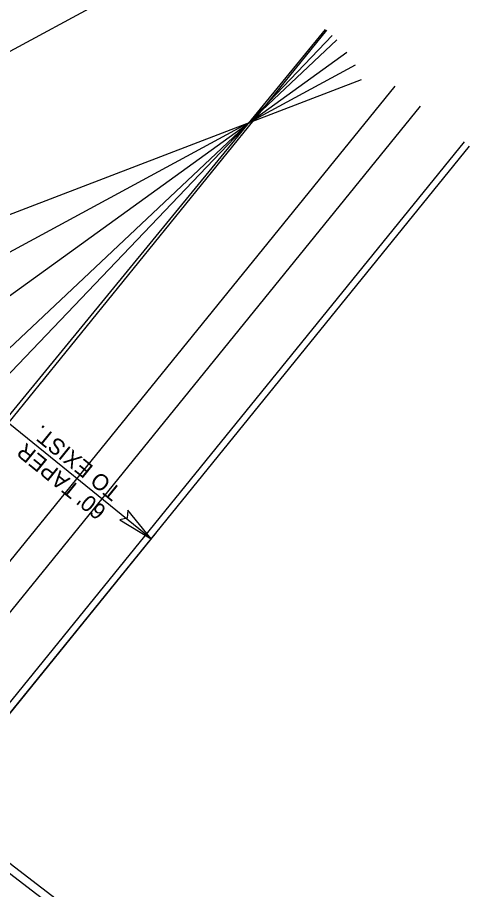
# Model space of a CAD drawing. Extents: x 1486489 to 1490134, y 497089 to 500876.
# Drawn here: x 1489056.4 to 1489168.8, y 499014.9 to 499231.7 of the extents above; entities that cross this region are included whole.
import ezdxf

# ---------------------------------------------------------------- set-up
doc = ezdxf.new("R2010")
doc.units = 0
for name, color, linetype in [('Prop Text', 7, 'Continuous'), ('Scratch_Level_5', 7, 'Continuous'), ('Sheet Border Standard 30in CELL', 7, 'Continuous'), ('Sheet Cutting Line CELL', 7, 'Continuous'), ('Sheet Plot Border Outside CELL', 7, 'Continuous'), ('Sheet Sticker Exception Certification CELL', 7, 'Continuous')]:
    doc.layers.add(name, color=color, linetype=linetype)

msp = doc.modelspace()

# ---------------------------------------------------------------- linework, layer by layer
at = {"layer": 'Prop Text'}
for p, q in [((1488858.52, 498937.81), (1489134.65, 499227.2)), ((1489133.24, 499228.47), (1488881.33, 498917.76)), ((1489156.48, 499209.63), (1488904.57, 498898.92)), ((1489167.42, 499200.76), (1488915.51, 498890.05)), ((1488916.88, 498888.94), (1489168.79, 499199.65))]:
    msp.add_line(p, q, dxfattribs=at)
msp.add_lwpolyline([(1488898.42, 498903.91), (1488898.42, 498903.91), (1489150.33, 499214.62)], dxfattribs=at)
at = {"layer": 'Scratch_Level_5'}
msp.add_lwpolyline([(1489042.71, 499028.27), (1489054.46, 499018.99), (1489094.18, 498988.49), (1489125.68, 498966.85), (1489130.23, 498964.14)], dxfattribs=at)
at = {"layer": 'Sheet Border Standard 30in CELL'}
for p, q in [((1489121.95, 499259.71), (1488770.16, 499069.32)), ((1488879.44, 498919.3), (1489132.96, 499228.7)), ((1489135.79, 499226.06), (1488844.47, 498951.95)), ((1488814, 498988.85), (1489138.26, 499223.06)), ((1489140.33, 499219.78), (1488788.55, 499029.37)), ((1488768.54, 499072.84), (1489141.95, 499216.25))]:
    msp.add_line(p, q, dxfattribs=at)
at = {"layer": 'Sheet Cutting Line CELL'}
for p, q in [((1489089.68, 499102.08), (1489047.72, 499136.1)), ((1489090.94, 499103.63), (1489050.58, 499053.85))]:
    msp.add_line(p, q, dxfattribs=at)
at = {"layer": 'Sheet Plot Border Outside CELL'}
msp.add_lwpolyline([(1489081.86, 499106.8), (1489089.68, 499102.08), (1489083.88, 499109.21), (1489083.7, 499107.25)], close=True, dxfattribs=at)
at = {"layer": 'Sheet Sticker Exception Certification CELL'}
msp.add_lwpolyline([(1489043.97, 499029.82), (1489055.69, 499020.57), (1489095.36, 498990.11), (1489126.76, 498968.54), (1489131.27, 498965.85)], dxfattribs=at)

# ---------------------------------------------------------------- texts
at = {"layer": 'Sheet Cutting Line CELL'}
for s, p in [('TO EXIST.', (1489082.48, 499114.36)), ("60' TAPER", (1489078.82, 499109.6))]:
    msp.add_text(s, height=4, rotation=140.9669, dxfattribs=at).set_placement(p)

doc.saveas('drawing.dxf')
